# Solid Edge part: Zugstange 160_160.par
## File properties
Username: ahadarics
Dokumentum tartalom típus: 0
Author: ahadarics
Last saved by: ahadarics
Revision: 83
Sűrűség: 0,000 kg/m^3
Pontosság: 0,990
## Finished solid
Body 1: solid body, 5 faces, 7 edges, 4 vertices.
  Faces by surface: cone 2, plane 2, cylinder 1
  Edges by curve: circle 5, line 2
Bounding box of the edges (mm): 16.000 x 16.000 x 290.000, from (-8, -8, -212.5) to (8, 8, 77.5).
Cylindrical faces by radius (mm): R8 x1
Conical faces (half-angle, radius in mm at the cone's reference point): 45 deg R7.5 x2
Planar faces by outward normal: +z 1, -z 1
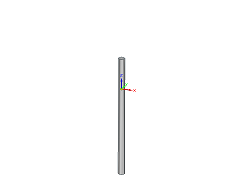
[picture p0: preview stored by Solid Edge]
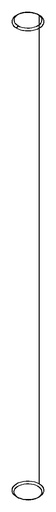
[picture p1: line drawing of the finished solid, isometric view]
